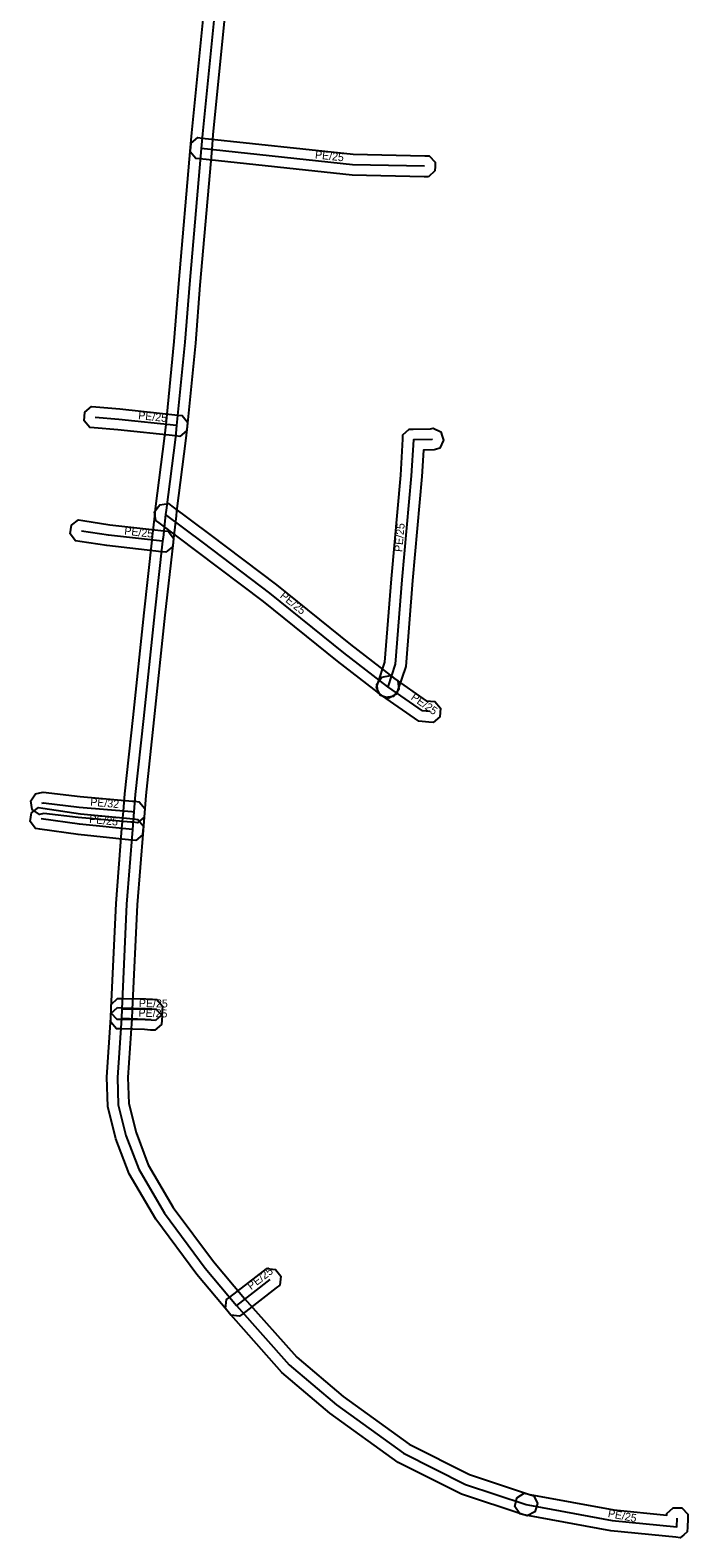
# Model space of a CAD drawing. Extents: x -681131 to -680872, y -1058347 to -1057759.
# Drawn here: x -681131.1 to -681068.8, y -1058347.1 to -1058204.3 of the extents above; entities that cross this region are included whole.
import ezdxf

# ---------------------------------------------------------------- set-up
doc = ezdxf.new("R2010")
doc.units = 0
for name, color, linetype in [('1', 7, 'Continuous'), ('24', 7, 'Continuous'), ('30', 7, 'Continuous')]:
    doc.layers.add(name, color=color, linetype=linetype)

msp = doc.modelspace()

# ---------------------------------------------------------------- linework, layer by layer
at = {"layer": '1'}
msp.add_lwpolyline([(-681112.68, -1058203.13), (-681113.78, -1058214.19), (-681113.9, -1058215.59), (-681115.02, -1058228.44), (-681115.45, -1058233.95), (-681116.23, -1058241.84), (-681116.35, -1058242.95), (-681117.23, -1058249.87), (-681117.28, -1058250.29), (-681117.52, -1058252.45), (-681117.56, -1058252.82), (-681118.33, -1058259.71), (-681119.37, -1058269.62), (-681120.14, -1058276.81), (-681120.27, -1058278.43), (-681120.4, -1058280.1), (-681120.96, -1058287.16), (-681121.42, -1058297.08), (-681121.46, -1058297.97), (-681121.84, -1058303.53), (-681121.75, -1058305.98), (-681121.07, -1058308.73), (-681119.92, -1058311.79), (-681117.54, -1058315.84), (-681113.73, -1058320.96), (-681110.8, -1058324.46), (-681105.85, -1058330.02), (-681101.46, -1058333.74), (-681095.2, -1058338.27), (-681089.49, -1058341.15), (-681083.8, -1058343.02), (-681083.4, -1058343.15), (-681083.03, -1058343.89), (-681083.16, -1058344.28), (-681083.29, -1058344.68), (-681084.03, -1058345.05), (-681084.42, -1058344.92), (-681090.25, -1058343.01), (-681096.24, -1058339.99), (-681102.7, -1058335.32), (-681107.25, -1058331.46), (-681112.32, -1058325.76), (-681115.31, -1058322.2), (-681119.2, -1058316.94), (-681121.72, -1058312.65), (-681122.99, -1058309.33), (-681123.75, -1058306.26), (-681123.84, -1058303.49), (-681123.46, -1058297.85), (-681123.42, -1058296.98), (-681122.96, -1058287.04), (-681122.4, -1058279.94), (-681122.27, -1058278.27), (-681122.14, -1058276.63), (-681121.35, -1058269.4), (-681120.31, -1058259.49), (-681119.54, -1058252.6), (-681119.5, -1058252.23), (-681119.26, -1058250.07), (-681119.21, -1058249.63), (-681118.33, -1058242.73), (-681118.22, -1058241.64), (-681117.45, -1058233.77), (-681117.02, -1058228.28), (-681115.9, -1058215.41), (-681115.78, -1058214.01), (-681114.68, -1058202.95)], dxfattribs=at)
for points in [[(-681093.35, -1058218.19), (-681093.76, -1058218.18), (-681100.61, -1058218.03), (-681115.01, -1058216.49), (-681115.42, -1058216.45), (-681115.94, -1058215.81), (-681115.89, -1058215.39), (-681115.85, -1058214.98), (-681115.21, -1058214.46), (-681114.79, -1058214.51), (-681100.49, -1058216.03), (-681093.72, -1058216.18), (-681093.3, -1058216.19), (-681092.73, -1058216.79), (-681092.74, -1058217.2), (-681092.75, -1058217.62)], [(-681116.92, -1058242.78), (-681117.34, -1058242.73), (-681122.79, -1058242.16), (-681125.03, -1058241.97), (-681125.45, -1058241.93), (-681125.98, -1058241.3), (-681125.95, -1058240.89), (-681125.91, -1058240.47), (-681125.28, -1058239.94), (-681124.87, -1058239.97), (-681122.59, -1058240.16), (-681117.12, -1058240.75), (-681116.71, -1058240.79), (-681116.19, -1058241.43), (-681116.24, -1058241.85), (-681116.28, -1058242.26)], [(-681094.82, -1058242.09), (-681093.18, -1058242.06), (-681092.93, -1058241.98), (-681092.19, -1058242.35), (-681092.06, -1058242.74), (-681091.93, -1058243.14), (-681092.3, -1058243.88), (-681092.69, -1058244.01), (-681092.84, -1058244.06), (-681093.85, -1058244.07), (-681093.99, -1058246.59), (-681094.88, -1058256.44), (-681095.52, -1058264.57), (-681096.26, -1058266.8), (-681096.39, -1058267.2), (-681097.13, -1058267.57), (-681097.52, -1058267.44), (-681097.92, -1058267.31), (-681098.29, -1058266.57), (-681098.16, -1058266.18), (-681097.5, -1058264.17), (-681096.88, -1058256.28), (-681095.99, -1058246.45), (-681095.8, -1058243.03), (-681095.78, -1058242.64), (-681095.21, -1058242.1)], [(-681097.49, -1058267.53), (-681097.82, -1058267.28), (-681102, -1058264.08), (-681109, -1058258.43), (-681115.29, -1058253.67), (-681118.87, -1058250.98), (-681119.2, -1058250.73), (-681119.32, -1058249.91), (-681119.07, -1058249.58), (-681118.82, -1058249.25), (-681118, -1058249.13), (-681117.67, -1058249.38), (-681114.09, -1058252.07), (-681107.76, -1058256.85), (-681100.76, -1058262.5), (-681096.6, -1058265.7), (-681096.27, -1058265.95), (-681096.17, -1058266.77), (-681096.42, -1058267.1), (-681096.67, -1058267.43)], [(-681118.25, -1058253.75), (-681118.66, -1058253.7), (-681123.82, -1058253.12), (-681126.4, -1058252.73), (-681126.81, -1058252.67), (-681127.3, -1058252), (-681127.24, -1058251.59), (-681127.18, -1058251.18), (-681126.51, -1058250.69), (-681126.1, -1058250.75), (-681123.56, -1058251.14), (-681118.44, -1058251.72), (-681118.03, -1058251.76), (-681117.51, -1058252.41), (-681117.56, -1058252.82), (-681117.6, -1058253.23)], [(-681092.93, -1058269.88), (-681093.34, -1058269.85), (-681094.29, -1058269.76), (-681097.78, -1058267.31), (-681098.12, -1058267.07), (-681098.27, -1058266.26), (-681098.03, -1058265.92), (-681097.79, -1058265.58), (-681096.97, -1058265.43), (-681096.64, -1058265.67), (-681093.58, -1058267.82), (-681093.16, -1058267.85), (-681092.75, -1058267.89), (-681092.22, -1058268.52), (-681092.25, -1058268.94), (-681092.29, -1058269.35)], [(-681130.58, -1058276.63), (-681130.17, -1058276.56), (-681129.87, -1058276.5), (-681126.35, -1058276.9), (-681121.4, -1058277.33), (-681121.39, -1058277.33), (-681121.18, -1058277.35), (-681120.77, -1058277.39), (-681120.24, -1058278.02), (-681120.27, -1058278.43), (-681120.31, -1058278.85), (-681120.94, -1058279.38), (-681121.35, -1058279.34), (-681121.54, -1058279.33), (-681121.56, -1058279.33), (-681126.55, -1058278.89), (-681129.79, -1058278.52), (-681129.81, -1058278.52), (-681130.21, -1058278.6), (-681130.9, -1058278.13), (-681130.97, -1058277.72), (-681131.05, -1058277.32)], [(-681121.09, -1058281.06), (-681121.5, -1058281.02), (-681126.56, -1058280.51), (-681130.19, -1058279.99), (-681130.6, -1058279.93), (-681131.1, -1058279.27), (-681131.04, -1058278.86), (-681130.98, -1058278.45), (-681130.32, -1058277.95), (-681129.91, -1058278.01), (-681126.32, -1058278.53), (-681121.3, -1058279.02), (-681120.89, -1058279.07), (-681120.36, -1058279.71), (-681120.41, -1058280.12), (-681120.45, -1058280.53)], [(-681122.84, -1058296.9), (-681122.43, -1058296.91), (-681120.16, -1058296.98), (-681119.56, -1058297.02), (-681119.15, -1058297.05), (-681118.6, -1058297.68), (-681118.63, -1058298.09), (-681118.66, -1058298.5), (-681119.29, -1058299.05), (-681119.7, -1058299.02), (-681120.26, -1058298.98), (-681122.49, -1058298.91), (-681122.91, -1058298.9), (-681123.47, -1058298.29), (-681123.46, -1058297.88), (-681123.45, -1058297.47)], [(-681119.23, -1058298.13), (-681119.65, -1058298.1), (-681120.21, -1058298.06), (-681122.43, -1058298.03), (-681122.85, -1058298.02), (-681123.43, -1058297.43), (-681123.42, -1058297.02), (-681123.42, -1058296.6), (-681122.82, -1058296.02), (-681122.41, -1058296.03), (-681120.13, -1058296.06), (-681119.51, -1058296.1), (-681119.1, -1058296.13), (-681118.55, -1058296.76), (-681118.58, -1058297.17), (-681118.61, -1058297.58)], [(-681107.45, -1058323.19), (-681107.78, -1058323.44), (-681110.95, -1058325.9), (-681111.27, -1058326.15), (-681112.1, -1058326.05), (-681112.35, -1058325.72), (-681112.6, -1058325.4), (-681112.5, -1058324.57), (-681112.17, -1058324.32), (-681109, -1058321.86), (-681108.68, -1058321.61), (-681107.85, -1058321.71), (-681107.6, -1058322.04), (-681107.35, -1058322.36)], [(-681075.82, -1058344.49), (-681070.8, -1058345), (-681070.79, -1058344.84), (-681070.19, -1058344.28), (-681069.77, -1058344.29), (-681069.36, -1058344.31), (-681068.8, -1058344.91), (-681068.81, -1058345.33), (-681068.84, -1058346.14), (-681068.86, -1058346.57), (-681069.18, -1058346.85), (-681069.51, -1058347.14), (-681069.94, -1058347.09), (-681076.1, -1058346.47), (-681084.15, -1058344.98), (-681084.32, -1058344.95), (-681084.72, -1058344.86), (-681085.17, -1058344.17), (-681085.09, -1058343.76), (-681085, -1058343.36), (-681084.31, -1058342.91), (-681083.9, -1058342.99), (-681083.76, -1058343.02)]]:
    msp.add_lwpolyline(points, close=True, dxfattribs=at)
at = {"layer": '24'}
for points in [[(-681113.68, -1058203.04), (-681114.78, -1058214.1), (-681114.9, -1058215.5), (-681116.02, -1058228.36), (-681116.45, -1058233.86), (-681117.23, -1058241.74), (-681117.34, -1058242.84), (-681118.22, -1058249.75), (-681118.27, -1058250.18), (-681118.51, -1058252.34), (-681118.55, -1058252.71), (-681119.32, -1058259.6), (-681120.36, -1058269.51), (-681121.14, -1058276.72), (-681121.27, -1058278.35), (-681121.4, -1058280.02), (-681121.96, -1058287.1), (-681122.42, -1058297.03), (-681122.46, -1058297.91), (-681122.84, -1058303.51), (-681122.75, -1058306.12), (-681122.03, -1058309.03), (-681120.82, -1058312.22), (-681118.37, -1058316.39), (-681114.52, -1058321.58), (-681111.56, -1058325.11), (-681106.55, -1058330.74), (-681102.08, -1058334.53), (-681095.72, -1058339.13), (-681089.87, -1058342.08), (-681084.11, -1058343.97)], [(-681093.74, -1058217.18), (-681100.55, -1058217.03), (-681114.9, -1058215.5)], [(-681117.23, -1058241.74), (-681122.69, -1058241.16), (-681124.95, -1058240.97)], [(-681093.01, -1058243.06), (-681093.01, -1058243.06), (-681094.8, -1058243.09), (-681094.99, -1058246.52), (-681095.88, -1058256.36), (-681096.51, -1058264.37), (-681097.21, -1058266.49)], [(-681097.21, -1058266.49), (-681101.38, -1058263.29), (-681108.38, -1058257.64), (-681114.69, -1058252.87), (-681118.27, -1058250.18)], [(-681118.55, -1058252.71), (-681123.69, -1058252.13), (-681126.25, -1058251.74)], [(-681093.25, -1058268.85), (-681093.93, -1058268.79), (-681097.21, -1058266.49)], [(-681129.99, -1058277.54), (-681129.83, -1058277.51), (-681126.45, -1058277.89), (-681121.48, -1058278.33), (-681121.46, -1058278.33), (-681121.27, -1058278.35)], [(-681121.4, -1058280.02), (-681126.44, -1058279.52), (-681130.05, -1058279)], [(-681119.58, -1058297.1), (-681120.17, -1058297.06), (-681122.42, -1058297.03)], [(-681122.46, -1058297.91), (-681120.93, -1058297.96), (-681120.21, -1058297.98), (-681119.63, -1058298.02)], [(-681108.39, -1058322.65), (-681111.56, -1058325.11)], [(-681084.11, -1058343.97), (-681083.96, -1058344), (-681075.96, -1058345.48), (-681069.84, -1058346.1), (-681069.81, -1058345.29)]]:
    msp.add_lwpolyline(points, dxfattribs=at)

# ---------------------------------------------------------------- texts
at = {"layer": '30'}
for s, rotation, p in [('PE/25', 353.9141, (-681104.14, -1058216.43)), ('PE/25', 353.9364, (-681120.89, -1058241.13)), ('PE/25', 353.562, (-681122.21, -1058252.07)), ('PE/25', 84.8318, (-681095.86, -1058253.75)), ('PE/25', 321.0915, (-681107.49, -1058257.99)), ('PE/25', 324.9611, (-681095.09, -1058267.64)), ('PE/32', 354.9407, (-681125.43, -1058277.76)), ('PE/25', 354.3344, (-681125.53, -1058279.39)), ('PE/25', 358.237, (-681120.84, -1058297.75)), ('PE/25', 359.2361, (-681120.8, -1058296.85)), ('PE/25', 37.8124, (-681110.17, -1058323.68)), ('PE/25', 349.5314, (-681076.41, -1058345.16))]:
    msp.add_text(s, height=0.75, rotation=rotation, dxfattribs=at).set_placement(p)

doc.saveas('drawing.dxf')
